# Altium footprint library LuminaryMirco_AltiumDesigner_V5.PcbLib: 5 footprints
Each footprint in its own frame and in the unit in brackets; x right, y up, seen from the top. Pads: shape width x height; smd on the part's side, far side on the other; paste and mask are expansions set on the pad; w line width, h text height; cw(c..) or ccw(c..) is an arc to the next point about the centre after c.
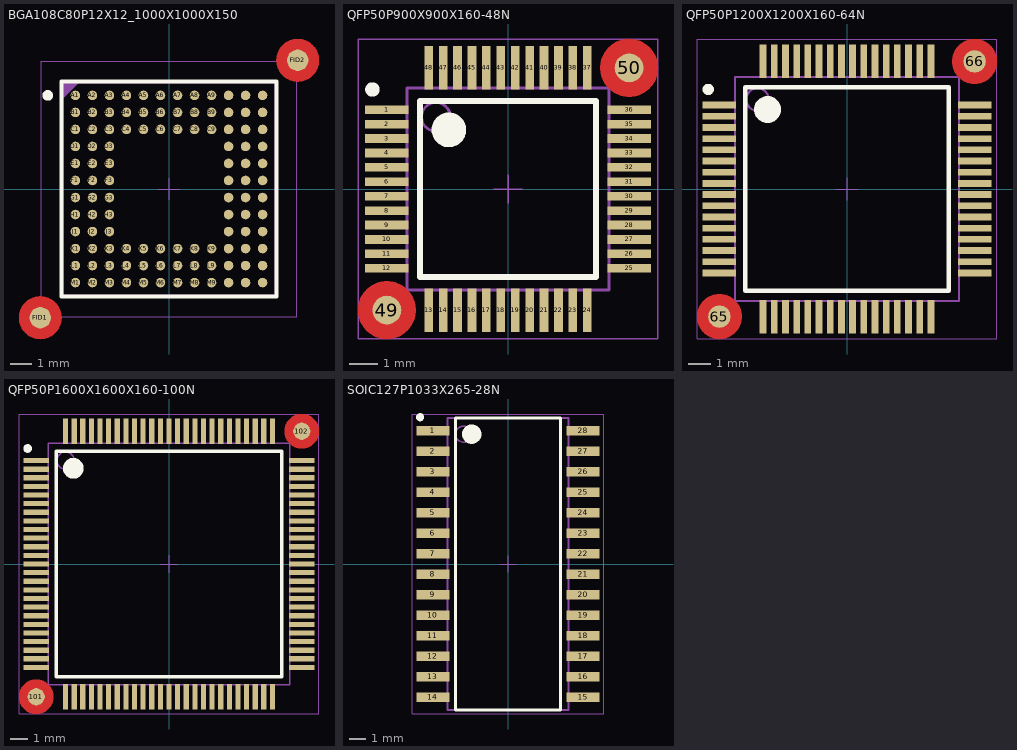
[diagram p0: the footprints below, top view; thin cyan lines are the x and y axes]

## BGA108C80P12X12_1000X1000X150 [mm] "BGA,0.80mm pitch,square;108 pin,12 columns X 12 rows,10.00mm X 10.00mm X 1.50mm H"
height 1.5
pads (110):
  round 0.45 smd: A1(-4.4,4.4) A2(-3.6,4.4) A3(-2.8,4.4) A4(-2,4.4) A5(-1.2,4.4) A6(-0.4,4.4) A7(0.4,4.4) A8(1.2,4.4) A9(2,4.4) A10(2.8,4.4) A11(3.6,4.4) A12(4.4,4.4) B1(-4.4,3.6) B2(-3.6,3.6) B3(-2.8,3.6) B4(-2,3.6) B5(-1.2,3.6) B6(-0.4,3.6) B7(0.4,3.6) B8(1.2,3.6) B9(2,3.6) B10(2.8,3.6) B11(3.6,3.6) B12(4.4,3.6) C1(-4.4,2.8) C2(-3.6,2.8) C3(-2.8,2.8) C4(-2,2.8) C5(-1.2,2.8) C6(-0.4,2.8) C7(0.4,2.8) C8(1.2,2.8) C9(2,2.8) C10(2.8,2.8) C11(3.6,2.8) C12(4.4,2.8) D1(-4.4,2) D2(-3.6,2) D3(-2.8,2) D10(2.8,2) D11(3.6,2) D12(4.4,2) E1(-4.4,1.2) E2(-3.6,1.2) E3(-2.8,1.2) E10(2.8,1.2) E11(3.6,1.2) E12(4.4,1.2) F1(-4.4,0.4) F2(-3.6,0.4) F3(-2.8,0.4) F10(2.8,0.4) F11(3.6,0.4) F12(4.4,0.4) G1(-4.4,-0.4) G2(-3.6,-0.4) G3(-2.8,-0.4) G10(2.8,-0.4) G11(3.6,-0.4) G12(4.4,-0.4) H1(-4.4,-1.2) H2(-3.6,-1.2) H3(-2.8,-1.2) H10(2.8,-1.2) H11(3.6,-1.2) H12(4.4,-1.2) J1(-4.4,-2) J2(-3.6,-2) J3(-2.8,-2) J10(2.8,-2) J11(3.6,-2) J12(4.4,-2) K1(-4.4,-2.8) K2(-3.6,-2.8) K3(-2.8,-2.8) K4(-2,-2.8) K5(-1.2,-2.8) K6(-0.4,-2.8) K7(0.4,-2.8) K8(1.2,-2.8) K9(2,-2.8) K10(2.8,-2.8) K11(3.6,-2.8) K12(4.4,-2.8) L1(-4.4,-3.6) L2(-3.6,-3.6) L3(-2.8,-3.6) L4(-2,-3.6) L5(-1.2,-3.6) L6(-0.4,-3.6) L7(0.4,-3.6) L8(1.2,-3.6) L9(2,-3.6) L10(2.8,-3.6) L11(3.6,-3.6) L12(4.4,-3.6) M1(-4.4,-4.4) M2(-3.6,-4.4) M3(-2.8,-4.4) M4(-2,-4.4) M5(-1.2,-4.4) M6(-0.4,-4.4) M7(0.4,-4.4) M8(1.2,-4.4) M9(2,-4.4) M10(2.8,-4.4) M11(3.6,-4.4) M12(4.4,-4.4)
  round 1 smd: FID1(-6.05,-6.05) FID2(6.05,6.05)
Top Layer:
  pour cut-out: 153 vertices and 0 holes, not listed, extent -7.05,-7.05 -5.05,-5.05
  pour cut-out: 153 vertices and 0 holes, not listed, extent 5.05,5.05 7.05,7.05
Top Overlay:
  circle w0.25: c-5.7,4.4 r0.125
  lines w0.2: -5.05,-5.05 5.05,-5.05 5.05,5.05 -5.05,5.05 -5.05,-5.05
Mechanical 12:
  lines w0.001: -5,-5 5,-5 5,5 -5,5 -5,-5
Mechanical 13:
  lines w0.1: -5,4.3 -4.3,5 ; -5,4.4 -4.4,5 ; -5,4.5 -4.5,5 ; -5,4.6 -4.6,5 ; -5,4.7 -4.7,5 ; -5,4.8 -4.8,5 ; -5,4.9 -4.9,5 ; -5,-5 5,-5 5,5 -5,5 -5,-5
  text ".Designator" at -0.518,-0.45 h0.75
Mechanical 15:
  lines w0.05: -0.5,0 0.5,0 ; 0,-0.5 0,0.5 ; -6,-6 6,-6 6,6 -6,6 -6,-6

## QFP50P900X900X160-48N [mm] "QFP,0.50mm pitch,square;12 pin X 12 pin,7.00mm X 7.00mm X 1.60mm H body"
height 1.6
pads (50):
  rect 1.5x0.3 smd: 1(-4.2,2.75) 2(-4.2,2.25) 3(-4.2,1.75) 4(-4.2,1.25) 5(-4.2,0.75) 6(-4.2,0.25) 7(-4.2,-0.25) 8(-4.2,-0.75) 9(-4.2,-1.25) 10(-4.2,-1.75) 11(-4.2,-2.25) 12(-4.2,-2.75) 25(4.2,-2.75) 26(4.2,-2.25) 27(4.2,-1.75) 28(4.2,-1.25) 29(4.2,-0.75) 30(4.2,-0.25) 31(4.2,0.25) 32(4.2,0.75) 33(4.2,1.25) 34(4.2,1.75) 35(4.2,2.25) 36(4.2,2.75)
  rect 0.3x1.5 smd: 13(-2.75,-4.2) 14(-2.25,-4.2) 15(-1.75,-4.2) 16(-1.25,-4.2) 17(-0.75,-4.2) 18(-0.25,-4.2) 19(0.25,-4.2) 20(0.75,-4.2) 21(1.25,-4.2) 22(1.75,-4.2) 23(2.25,-4.2) 24(2.75,-4.2) 37(2.75,4.2) 38(2.25,4.2) 39(1.75,4.2) 40(1.25,4.2) 41(0.75,4.2) 42(0.25,4.2) 43(-0.25,4.2) 44(-0.75,4.2) 45(-1.25,4.2) 46(-1.75,4.2) 47(-2.25,4.2) 48(-2.75,4.2)
  round 1 smd: 49(-4.2,-4.2) 50(4.2,4.2)
Top Layer:
  pour cut-out: 153 vertices and 0 holes, not listed, extent -5.2,-5.2 -3.2,-3.2
  pour cut-out: 153 vertices and 0 holes, not listed, extent 3.2,3.2 5.2,5.2
Top Overlay:
  circle w0.6: c-2.05,2.05 r0.3
  circle w0.25: c-4.7,3.45 r0.125
  lines w0.2: -3.05,-3.05 3.05,-3.05 3.05,3.05 -3.05,3.05 -3.05,-3.05
Mechanical 12:
  lines w0.001: -3.5,-3.5 3.5,-3.5 3.5,3.5 -3.5,3.5 -3.5,-3.5
Mechanical 13:
  circle w0.1: c-2.5,2.5 r0.5
  lines w0.1: -3.5,-3.5 3.5,-3.5 3.5,3.5 -3.5,3.5 -3.5,-3.5
  text ".Designator" at -0.696,-0.45 h0.75
Mechanical 15:
  lines w0.05: -0.5,0 0.5,0 ; 0,-0.5 0,0.5 ; -5.2,-5.2 5.2,-5.2 5.2,5.2 -5.2,5.2 -5.2,-5.2

## QFP50P1200X1200X160-64N [mm] "QFP,0.50mm pitch,square;16 pin X 16 pin,10.00mm X 10.00mm X 1.60mm H body"
height 1.6
pads (66):
  rect 1.5x0.3 smd: 1(-5.7,3.75) 2(-5.7,3.25) 3(-5.7,2.75) 4(-5.7,2.25) 5(-5.7,1.75) 6(-5.7,1.25) 7(-5.7,0.75) 8(-5.7,0.25) 9(-5.7,-0.25) 10(-5.7,-0.75) 11(-5.7,-1.25) 12(-5.7,-1.75) 13(-5.7,-2.25) 14(-5.7,-2.75) 15(-5.7,-3.25) 16(-5.7,-3.75) 33(5.7,-3.75) 34(5.7,-3.25) 35(5.7,-2.75) 36(5.7,-2.25) 37(5.7,-1.75) 38(5.7,-1.25) 39(5.7,-0.75) 40(5.7,-0.25) 41(5.7,0.25) 42(5.7,0.75) 43(5.7,1.25) 44(5.7,1.75) 45(5.7,2.25) 46(5.7,2.75) 47(5.7,3.25) 48(5.7,3.75)
  rect 0.3x1.5 smd: 17(-3.75,-5.7) 18(-3.25,-5.7) 19(-2.75,-5.7) 20(-2.25,-5.7) 21(-1.75,-5.7) 22(-1.25,-5.7) 23(-0.75,-5.7) 24(-0.25,-5.7) 25(0.25,-5.7) 26(0.75,-5.7) 27(1.25,-5.7) 28(1.75,-5.7) 29(2.25,-5.7) 30(2.75,-5.7) 31(3.25,-5.7) 32(3.75,-5.7) 49(3.75,5.7) 50(3.25,5.7) 51(2.75,5.7) 52(2.25,5.7) 53(1.75,5.7) 54(1.25,5.7) 55(0.75,5.7) 56(0.25,5.7) 57(-0.25,5.7) 58(-0.75,5.7) 59(-1.25,5.7) 60(-1.75,5.7) 61(-2.25,5.7) 62(-2.75,5.7) 63(-3.25,5.7) 64(-3.75,5.7)
  round 1 smd: 65(-5.7,-5.7) 66(5.7,5.7)
Top Layer:
  pour cut-out: 153 vertices and 0 holes, not listed, extent -6.7,-6.7 -4.7,-4.7
  pour cut-out: 153 vertices and 0 holes, not listed, extent 4.7,4.7 6.7,6.7
Top Overlay:
  circle w0.6: c-3.55,3.55 r0.3
  circle w0.25: c-6.2,4.45 r0.125
  lines w0.2: -4.55,-4.55 4.55,-4.55 4.55,4.55 -4.55,4.55 -4.55,-4.55
Mechanical 12:
  lines w0.001: -5,-5 5,-5 5,5 -5,5 -5,-5
Mechanical 13:
  circle w0.1: c-4,4 r0.5
  lines w0.1: -5,-5 5,-5 5,5 -5,5 -5,-5
  text ".Designator" at -0.678,-0.45 h0.75
Mechanical 15:
  lines w0.05: -0.5,0 0.5,0 ; 0,-0.5 0,0.5 ; -6.7,-6.7 6.7,-6.7 6.7,6.7 -6.7,6.7 -6.7,-6.7

## QFP50P1600X1600X160-100N [mm] "QFP,0.50mm pitch,square;25 pin X 25 pin,14.00mm X 14.00mm X 1.60mm H body"
height 1.6
pads (102):
  rect 1.5x0.3 smd: 1(-7.7,6) 2(-7.7,5.5) 3(-7.7,5) 4(-7.7,4.5) 5(-7.7,4) 6(-7.7,3.5) 7(-7.7,3) 8(-7.7,2.5) 9(-7.7,2) 10(-7.7,1.5) 11(-7.7,1) 12(-7.7,0.5) 13(-7.7,0) 14(-7.7,-0.5) 15(-7.7,-1) 16(-7.7,-1.5) 17(-7.7,-2) 18(-7.7,-2.5) 19(-7.7,-3) 20(-7.7,-3.5) 21(-7.7,-4) 22(-7.7,-4.5) 23(-7.7,-5) 24(-7.7,-5.5) 25(-7.7,-6) 51(7.7,-6) 52(7.7,-5.5) 53(7.7,-5) 54(7.7,-4.5) 55(7.7,-4) 56(7.7,-3.5) 57(7.7,-3) 58(7.7,-2.5) 59(7.7,-2) 60(7.7,-1.5) 61(7.7,-1) 62(7.7,-0.5) 63(7.7,0) 64(7.7,0.5) 65(7.7,1) 66(7.7,1.5) 67(7.7,2) 68(7.7,2.5) 69(7.7,3) 70(7.7,3.5) 71(7.7,4) 72(7.7,4.5) 73(7.7,5) 74(7.7,5.5) 75(7.7,6)
  rect 0.3x1.5 smd: 26(-6,-7.7) 27(-5.5,-7.7) 28(-5,-7.7) 29(-4.5,-7.7) 30(-4,-7.7) 31(-3.5,-7.7) 32(-3,-7.7) 33(-2.5,-7.7) 34(-2,-7.7) 35(-1.5,-7.7) 36(-1,-7.7) 37(-0.5,-7.7) 38(0,-7.7) 39(0.5,-7.7) 40(1,-7.7) 41(1.5,-7.7) 42(2,-7.7) 43(2.5,-7.7) 44(3,-7.7) 45(3.5,-7.7) 46(4,-7.7) 47(4.5,-7.7) 48(5,-7.7) 49(5.5,-7.7) 50(6,-7.7) 76(6,7.7) 77(5.5,7.7) 78(5,7.7) 79(4.5,7.7) 80(4,7.7) 81(3.5,7.7) 82(3,7.7) 83(2.5,7.7) 84(2,7.7) 85(1.5,7.7) 86(1,7.7) 87(0.5,7.7) 88(0,7.7) 89(-0.5,7.7) 90(-1,7.7) 91(-1.5,7.7) 92(-2,7.7) 93(-2.5,7.7) 94(-3,7.7) 95(-3.5,7.7) 96(-4,7.7) 97(-4.5,7.7) 98(-5,7.7) 99(-5.5,7.7) 100(-6,7.7)
  round 1 smd: 101(-7.7,-7.7) 102(7.7,7.7)
Top Layer:
  pour cut-out: 153 vertices and 0 holes, not listed, extent -8.7,-8.7 -6.7,-6.7
  pour cut-out: 153 vertices and 0 holes, not listed, extent 6.7,6.7 8.7,8.7
Top Overlay:
  circle w0.6: c-5.55,5.55 r0.3
  circle w0.25: c-8.2,6.7 r0.125
  lines w0.2: -6.55,-6.55 6.55,-6.55 6.55,6.55 -6.55,6.55 -6.55,-6.55
Mechanical 12:
  lines w0.001: -7,-7 7,-7 7,7 -7,7 -7,-7
Mechanical 13:
  circle w0.1: c-6,6 r0.5
  lines w0.1: -7,-7 7,-7 7,7 -7,7 -7,-7
  text ".Designator" at -0.678,-0.45 h0.75
Mechanical 15:
  lines w0.05: -0.5,0 0.5,0 ; 0,-0.5 0,0.5 ; -8.7,-8.7 8.7,-8.7 8.7,8.7 -8.7,8.7 -8.7,-8.7

## SOIC127P1033X265-28N [mm] "SOIC,1.27mm pitch;28 pin,7.50mm W X 18.10mm L X 2.65mm H body"
height 2.65
pads (28):
  rect 2.05x0.6 smd: 1(-4.65,8.255) 2(-4.65,6.985) 3(-4.65,5.715) 4(-4.65,4.445) 5(-4.65,3.175) 6(-4.65,1.905) 7(-4.65,0.635) 8(-4.65,-0.635) 9(-4.65,-1.905) 10(-4.65,-3.175) 11(-4.65,-4.445) 12(-4.65,-5.715) 13(-4.65,-6.985) 14(-4.65,-8.255) 15(4.65,-8.255) 16(4.65,-6.985) 17(4.65,-5.715) 18(4.65,-4.445) 19(4.65,-3.175) 20(4.65,-1.905) 21(4.65,-0.635) 22(4.65,0.635) 23(4.65,1.905) 24(4.65,3.175) 25(4.65,4.445) 26(4.65,5.715) 27(4.65,6.985) 28(4.65,8.255)
Top Overlay:
  circle w0.25: c-5.45,9.1 r0.125
  circle w0.6: c-2.25,8.05 r0.3
  lines w0.2: -3.25,-9.05 3.25,-9.05 3.25,9.05 -3.25,9.05 -3.25,-9.05
Mechanical 12:
  lines w0.001: -3.75,-9.05 3.75,-9.05 3.75,9.05 -3.75,9.05 -3.75,-9.05
Mechanical 13:
  circle w0.1: c-2.75,8.05 r0.5
  lines w0.1: -3.75,-9.05 3.75,-9.05 3.75,9.05 -3.75,9.05 -3.75,-9.05
  text ".Designator" at 0.45,-0.678 h0.75
Mechanical 15:
  lines w0.05: -0.5,0 0.5,0 ; 0,-0.5 0,0.5 ; -5.95,-9.3 5.95,-9.3 5.95,9.3 -5.95,9.3 -5.95,-9.3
